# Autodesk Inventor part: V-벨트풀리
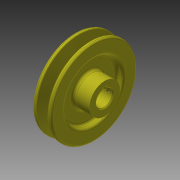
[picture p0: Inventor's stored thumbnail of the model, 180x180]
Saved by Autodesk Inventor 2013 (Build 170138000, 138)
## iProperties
Created: 2015-09
Part Number: V-벨트풀리
Material: 강철, 연강
Document SubType Name: Modeling
Designer: mduedu
Density: 7.86 g/cm^3
Mass: 779.014 g
Surface Area: 277.465 cm^2
Volume: 99.1112 cm^3
Author: mduedu
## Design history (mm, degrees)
sketch "스케치1"
  geometry: L1 (-10, 0)-(10, 0); L2 (-10, 0)-(-10, 45); L3 (-10, 45)-(-5.976, 45); L4 (-5.976, 45)-(-2.154, 32.5); L5 (-2.154, 32.5)-(2.154, 32.5); L6 (2.154, 32.5)-(5.976, 45); L7 (5.976, 45)-(10, 45); L8 (10, 45)-(10, 0); L9 (0, 0)-(0, 32.5); L10 (-10, 40.5)-(10, 40.5); 3 further points
  constraints: 20 end point, 6 point on line, 3 perpendicular, 2 midpoint, 2 parallel, 2 symmetric about line, 1 coincident, 1 collinear, 1 equal length, 1 horizontal, 1 vertical, 1 vertical alignment
  dimensions: "d0" = 20 distance between parallel lines of L8 L2; "d2" = 90 diameter of L3 L1; "d5" = 8 distance between parallel lines of L5 L10; "d6" = 9.2 distance of point (4.6, 40.5) point (-4.6, 40.5); "d7" = 34 deg angle of L6 L4; "d40" = 4.5 distance between parallel lines of L3 L10
revolve "회전1" sketch "스케치1" stored, may be unused: angle "d8" = 90 deg
sketch "스케치2"
  geometry: C1 r 16 at (0, 0); 1 further point
  constraints: 1 centre point, 1 coincident
  dimensions: "d9" = 32 diameter of C1
extrude "돌출1" join sketch "스케치2" distance "d10" = 11; taper "d11" = 0 deg
fillet "모깎기1" dims "d12" = 1, "d13" = 0.5, "d14" = 2
sketch "스케치3"
  geometry: C1 r 16 at (0, 0) reference; C2 r 30 at (0, 0); 1 further point
  constraints: 1 centre point, 1 coincident
  dimensions: "d15" = 60 diameter of C2
extrude "돌출2" cut sketch "스케치3" distance "d16" = 6; taper "d17" = 0 deg
fillet "모깎기2" dims "d18" = 3
fillet "모깎기3" dims "d19" = 3
fillet "모깎기4" dims "d20" = 3
sketch "스케치4"
  geometry: C1 r 8.5 at (0, 0); 1 further point
  constraints: 1 centre point, 1 coincident
  dimensions: "d21" = 17 diameter of C1
extrude "돌출3" cut sketch "스케치4" stored distance "d22" = 4; taper "d23" = 0 deg
sketch "스케치5"
  geometry: L1 (-2.5, 8.124)-(2.5, 8.124); L2 (2.5, 8.124)-(2.5, 10.8); L3 (2.5, 10.8)-(-2.5, 10.8); L4 (-2.5, 10.8)-(-2.5, 8.124); A1 r 8.5 centre (0, 0) between (-2.5, 8.124) and (2.5, 8.124) reference; 2 further points
  constraints: 8 end point, 3 point on circle, 2 parallel, 1 horizontal, 1 perpendicular, 1 vertical alignment
  dimensions: "d24" = 5 distance of L2.end L3.end; "d26" = 19.3 distance from line of L3 point (0, -8.5)
extrude "돌출4" cut sketch "스케치5" stored distance "d27" = 4; taper "d28" = 0 deg
chamfer "모따기1" distance "d29" = 1; stored, may be unused: second distance "d30" = 2, angle "d31" = 45 deg
node "작업 평면1"
sketch "스케치6"
  geometry: L1 (-11, 16)-(-11, -16) reference; 2 further points
  constraints: 1 horizontal alignment
  dimensions: "d32" = 5 distance from line of point (-6, 0) L1
hole "구멍1" sketch "스케치6" at (-6, 0) diameter "d33" = 3.242; stored, may be unused: countersink angle "d37" = 90 deg, drill point angle "d39" = 118 deg; dims "d34" = 6, "d35" = 4, "d36" = 2, "d38" = 8
node "솔리드1"
mirror "대칭1"
